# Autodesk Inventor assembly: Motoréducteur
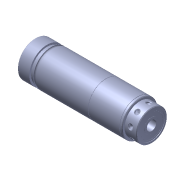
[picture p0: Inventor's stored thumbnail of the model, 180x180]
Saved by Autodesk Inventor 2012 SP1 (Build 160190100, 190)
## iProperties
Created: 2014-12
Part Number: Motoréducteur
Document SubType Name: Assembly
Designer: Bruno
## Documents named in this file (3)
- D:\Cours\Systèmes\secateur-hydrogene-Pragma\Documentation\Dossier technique Infaco F3005\Solidworks\Composants importés\F3005\Motoréducteur.iam
- D:\Cours\Systèmes\secateur-hydrogene-Pragma\Documentation\Dossier technique Infaco F3005\Solidworks\Composants importés\F3005\Roulement reducteur.ipt
- D:\Cours\Systèmes\secateur-hydrogene-Pragma\Documentation\Dossier technique Infaco F3005\Solidworks\Composants importés\F3005\Tube moteur.ipt
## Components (2 placed, 2 different names)
1. Roulement reducteur:1
2. Tube moteur:1
